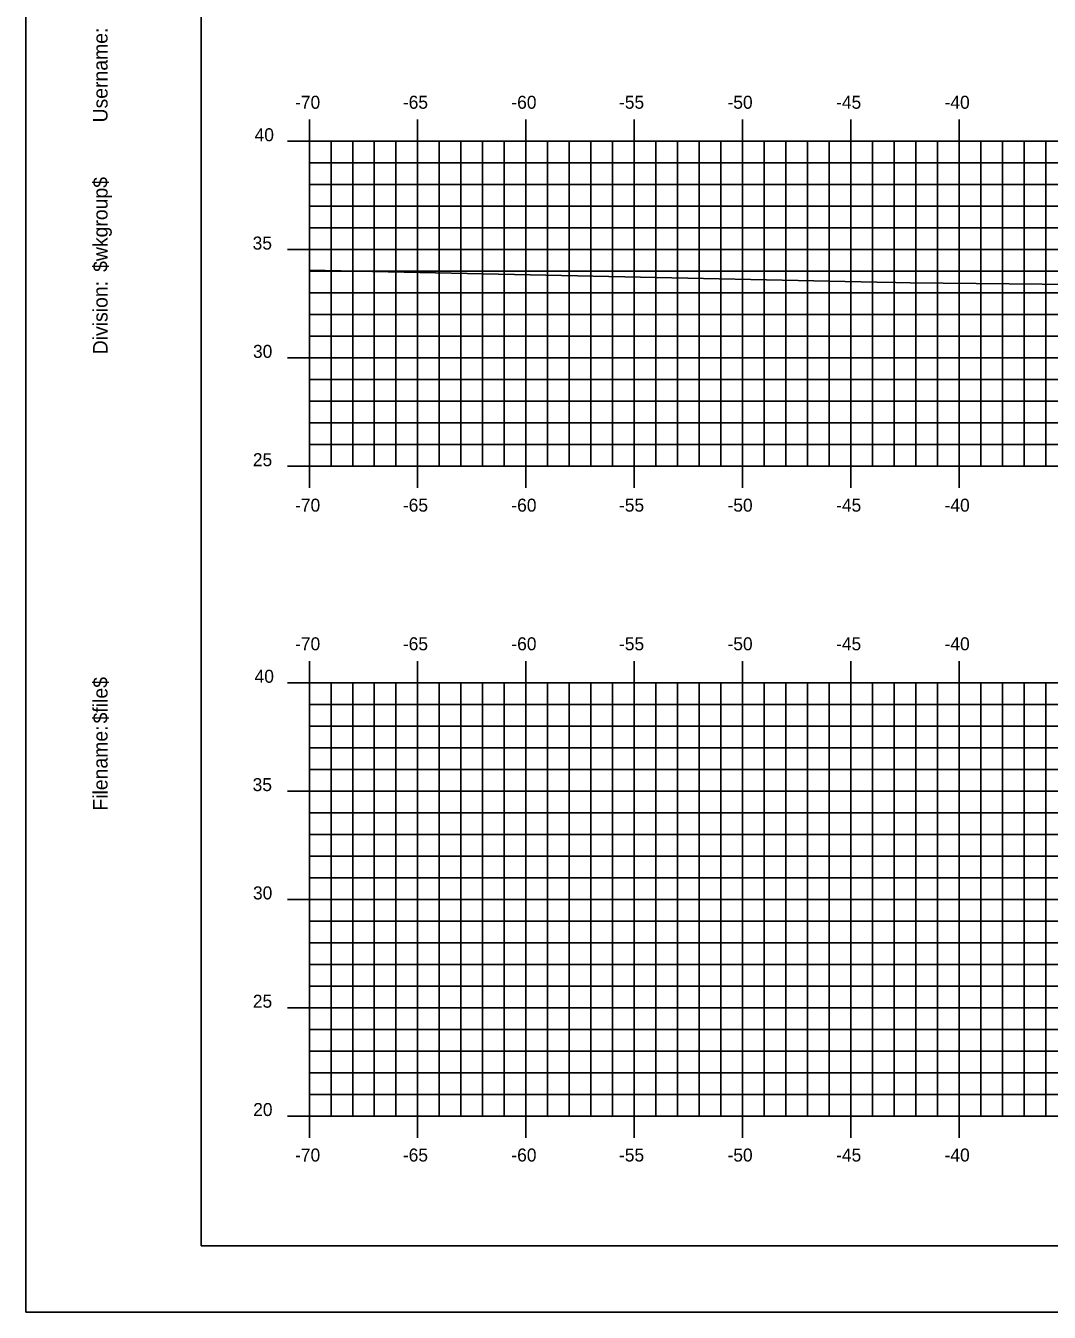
# Model space of a CAD drawing. Extents: x 1024350 to 1024520, y 394697 to 394807.
# Drawn here: x 1024349.9 to 1024397.2, y 394696.5 to 394755.9 of the extents above; entities that cross this region are included whole.
import ezdxf

# ---------------------------------------------------------------- set-up
doc = ezdxf.new("R2010")
doc.units = 0
for name, color, linetype in [('BORDER', 7, 'Continuous'), ('H_V ANNOTATION', 7, 'Continuous'), ('MAJOR', 7, 'Continuous'), ('MINOR', 7, 'Continuous'), ('PLOT BOUNDARY', 7, 'Continuous'), ('S_Roadway_Centerline', 7, 'Continuous')]:
    doc.layers.add(name, color=color, linetype=linetype)

msp = doc.modelspace()

# ---------------------------------------------------------------- linework, layer by layer
at = {"layer": 'BORDER'}
for p, q in [((1024358.002, 394804.607), (1024358.002, 394699.607)), ((1024358.002, 394699.607), (1024518.002, 394699.607))]:
    msp.add_line(p, q, dxfattribs=at)
at = {"layer": 'MAJOR'}
for p, q in [((1024363.002, 394751.609), (1024363.002, 394750.607)), ((1024368.002, 394751.609), (1024368.002, 394750.607)), ((1024373.002, 394751.609), (1024373.002, 394750.607)), ((1024378.002, 394751.609), (1024378.002, 394750.607)), ((1024383.002, 394751.609), (1024383.002, 394750.607)), ((1024388.002, 394751.609), (1024388.002, 394750.607)), ((1024393.002, 394751.609), (1024393.002, 394750.607)), ((1024362, 394750.607), (1024363.002, 394750.607)), ((1024363.002, 394750.607), (1024503.002, 394750.607)), ((1024363.002, 394735.607), (1024363.002, 394750.607)), ((1024368.002, 394735.607), (1024368.002, 394750.607)), ((1024373.002, 394735.607), (1024373.002, 394750.607)), ((1024378.002, 394735.607), (1024378.002, 394750.607)), ((1024383.002, 394735.607), (1024383.002, 394750.607)), ((1024388.002, 394735.607), (1024388.002, 394750.607)), ((1024393.002, 394735.607), (1024393.002, 394750.607)), ((1024362, 394745.607), (1024363.002, 394745.607)), ((1024363.002, 394745.607), (1024503.002, 394745.607)), ((1024362, 394740.607), (1024363.002, 394740.607)), ((1024363.002, 394740.607), (1024503.002, 394740.607)), ((1024362, 394735.607), (1024363.002, 394735.607)), ((1024363.002, 394735.607), (1024503.002, 394735.607)), ((1024363.002, 394734.605), (1024363.002, 394735.607)), ((1024368.002, 394734.605), (1024368.002, 394735.607)), ((1024373.002, 394734.605), (1024373.002, 394735.607)), ((1024378.002, 394734.605), (1024378.002, 394735.607)), ((1024383.002, 394734.605), (1024383.002, 394735.607)), ((1024388.002, 394734.605), (1024388.002, 394735.607)), ((1024393.002, 394734.605), (1024393.002, 394735.607)), ((1024363.002, 394726.609), (1024363.002, 394725.607)), ((1024368.002, 394726.609), (1024368.002, 394725.607)), ((1024373.002, 394726.609), (1024373.002, 394725.607)), ((1024378.002, 394726.609), (1024378.002, 394725.607)), ((1024383.002, 394726.609), (1024383.002, 394725.607)), ((1024388.002, 394726.609), (1024388.002, 394725.607)), ((1024393.002, 394726.609), (1024393.002, 394725.607)), ((1024362, 394725.607), (1024363.002, 394725.607)), ((1024363.002, 394725.607), (1024503.002, 394725.607)), ((1024363.002, 394705.607), (1024363.002, 394725.607)), ((1024368.002, 394705.607), (1024368.002, 394725.607)), ((1024373.002, 394705.607), (1024373.002, 394725.607)), ((1024378.002, 394705.607), (1024378.002, 394725.607)), ((1024383.002, 394705.607), (1024383.002, 394725.607)), ((1024388.002, 394705.607), (1024388.002, 394725.607)), ((1024393.002, 394705.607), (1024393.002, 394725.607)), ((1024362, 394720.607), (1024363.002, 394720.607)), ((1024363.002, 394720.607), (1024503.002, 394720.607)), ((1024362, 394715.607), (1024363.002, 394715.607)), ((1024363.002, 394715.607), (1024503.002, 394715.607)), ((1024362, 394710.607), (1024363.002, 394710.607)), ((1024363.002, 394710.607), (1024503.002, 394710.607)), ((1024362, 394705.607), (1024363.002, 394705.607)), ((1024363.002, 394705.607), (1024503.002, 394705.607)), ((1024363.002, 394704.605), (1024363.002, 394705.607)), ((1024368.002, 394704.605), (1024368.002, 394705.607)), ((1024373.002, 394704.605), (1024373.002, 394705.607)), ((1024378.002, 394704.605), (1024378.002, 394705.607)), ((1024383.002, 394704.605), (1024383.002, 394705.607)), ((1024388.002, 394704.605), (1024388.002, 394705.607)), ((1024393.002, 394704.605), (1024393.002, 394705.607))]:
    msp.add_line(p, q, dxfattribs=at)
at = {"layer": 'MINOR'}
for p, q in [((1024364.002, 394735.607), (1024364.002, 394750.607)), ((1024365.002, 394735.607), (1024365.002, 394750.607)), ((1024366.002, 394735.607), (1024366.002, 394750.607)), ((1024367.002, 394735.607), (1024367.002, 394750.607)), ((1024369.002, 394735.607), (1024369.002, 394750.607)), ((1024370.002, 394735.607), (1024370.002, 394750.607)), ((1024371.002, 394735.607), (1024371.002, 394750.607)), ((1024372.002, 394735.607), (1024372.002, 394750.607)), ((1024374.002, 394735.607), (1024374.002, 394750.607)), ((1024375.002, 394735.607), (1024375.002, 394750.607)), ((1024376.002, 394735.607), (1024376.002, 394750.607)), ((1024377.002, 394735.607), (1024377.002, 394750.607)), ((1024379.002, 394735.607), (1024379.002, 394750.607)), ((1024380.002, 394735.607), (1024380.002, 394750.607)), ((1024381.002, 394735.607), (1024381.002, 394750.607)), ((1024382.002, 394735.607), (1024382.002, 394750.607)), ((1024384.002, 394735.607), (1024384.002, 394750.607)), ((1024385.002, 394735.607), (1024385.002, 394750.607)), ((1024386.002, 394735.607), (1024386.002, 394750.607)), ((1024387.002, 394735.607), (1024387.002, 394750.607)), ((1024389.002, 394735.607), (1024389.002, 394750.607)), ((1024390.002, 394735.607), (1024390.002, 394750.607)), ((1024391.002, 394735.607), (1024391.002, 394750.607)), ((1024392.002, 394735.607), (1024392.002, 394750.607)), ((1024394.002, 394735.607), (1024394.002, 394750.607)), ((1024395.002, 394735.607), (1024395.002, 394750.607)), ((1024396.002, 394735.607), (1024396.002, 394750.607)), ((1024397.002, 394735.607), (1024397.002, 394750.607)), ((1024363.002, 394749.607), (1024503.002, 394749.607)), ((1024363.002, 394749.607), (1024364.004, 394749.607)), ((1024363.002, 394748.607), (1024503.002, 394748.607)), ((1024363.002, 394748.607), (1024364.004, 394748.607)), ((1024363.002, 394747.607), (1024503.002, 394747.607)), ((1024363.002, 394747.607), (1024364.004, 394747.607)), ((1024363.002, 394746.607), (1024503.002, 394746.607)), ((1024363.002, 394746.607), (1024364.004, 394746.607)), ((1024363.002, 394744.607), (1024503.002, 394744.607)), ((1024363.002, 394744.607), (1024364.004, 394744.607)), ((1024363.002, 394743.607), (1024503.002, 394743.607)), ((1024363.002, 394743.607), (1024364.004, 394743.607)), ((1024363.002, 394742.607), (1024503.002, 394742.607)), ((1024363.002, 394742.607), (1024364.004, 394742.607)), ((1024363.002, 394741.607), (1024503.002, 394741.607)), ((1024363.002, 394741.607), (1024364.004, 394741.607)), ((1024363.002, 394739.607), (1024503.002, 394739.607)), ((1024363.002, 394739.607), (1024364.004, 394739.607)), ((1024363.002, 394738.607), (1024503.002, 394738.607)), ((1024363.002, 394738.607), (1024364.004, 394738.607)), ((1024363.002, 394737.607), (1024503.002, 394737.607)), ((1024363.002, 394737.607), (1024364.004, 394737.607)), ((1024363.002, 394736.607), (1024503.002, 394736.607)), ((1024363.002, 394736.607), (1024364.004, 394736.607)), ((1024364.002, 394705.607), (1024364.002, 394725.607)), ((1024365.002, 394705.607), (1024365.002, 394725.607)), ((1024366.002, 394705.607), (1024366.002, 394725.607)), ((1024367.002, 394705.607), (1024367.002, 394725.607)), ((1024369.002, 394705.607), (1024369.002, 394725.607)), ((1024370.002, 394705.607), (1024370.002, 394725.607)), ((1024371.002, 394705.607), (1024371.002, 394725.607)), ((1024372.002, 394705.607), (1024372.002, 394725.607)), ((1024374.002, 394705.607), (1024374.002, 394725.607)), ((1024375.002, 394705.607), (1024375.002, 394725.607)), ((1024376.002, 394705.607), (1024376.002, 394725.607)), ((1024377.002, 394705.607), (1024377.002, 394725.607)), ((1024379.002, 394705.607), (1024379.002, 394725.607)), ((1024380.002, 394705.607), (1024380.002, 394725.607)), ((1024381.002, 394705.607), (1024381.002, 394725.607)), ((1024382.002, 394705.607), (1024382.002, 394725.607)), ((1024384.002, 394705.607), (1024384.002, 394725.607)), ((1024385.002, 394705.607), (1024385.002, 394725.607)), ((1024386.002, 394705.607), (1024386.002, 394725.607)), ((1024387.002, 394705.607), (1024387.002, 394725.607)), ((1024389.002, 394705.607), (1024389.002, 394725.607)), ((1024390.002, 394705.607), (1024390.002, 394725.607)), ((1024391.002, 394705.607), (1024391.002, 394725.607)), ((1024392.002, 394705.607), (1024392.002, 394725.607)), ((1024394.002, 394705.607), (1024394.002, 394725.607)), ((1024395.002, 394705.607), (1024395.002, 394725.607)), ((1024396.002, 394705.607), (1024396.002, 394725.607)), ((1024397.002, 394705.607), (1024397.002, 394725.607)), ((1024363.002, 394724.607), (1024503.002, 394724.607)), ((1024363.002, 394724.607), (1024364.004, 394724.607)), ((1024363.002, 394723.607), (1024503.002, 394723.607)), ((1024363.002, 394723.607), (1024364.004, 394723.607)), ((1024363.002, 394722.607), (1024503.002, 394722.607)), ((1024363.002, 394722.607), (1024364.004, 394722.607)), ((1024363.002, 394721.607), (1024503.002, 394721.607)), ((1024363.002, 394721.607), (1024364.004, 394721.607)), ((1024363.002, 394719.607), (1024503.002, 394719.607)), ((1024363.002, 394719.607), (1024364.004, 394719.607)), ((1024363.002, 394718.607), (1024503.002, 394718.607)), ((1024363.002, 394718.607), (1024364.004, 394718.607)), ((1024363.002, 394717.607), (1024503.002, 394717.607)), ((1024363.002, 394717.607), (1024364.004, 394717.607)), ((1024363.002, 394716.607), (1024503.002, 394716.607)), ((1024363.002, 394716.607), (1024364.004, 394716.607)), ((1024363.002, 394714.607), (1024503.002, 394714.607)), ((1024363.002, 394714.607), (1024364.004, 394714.607)), ((1024363.002, 394713.607), (1024503.002, 394713.607)), ((1024363.002, 394713.607), (1024364.004, 394713.607)), ((1024363.002, 394712.607), (1024503.002, 394712.607)), ((1024363.002, 394712.607), (1024364.004, 394712.607)), ((1024363.002, 394711.607), (1024503.002, 394711.607)), ((1024363.002, 394711.607), (1024364.004, 394711.607)), ((1024363.002, 394709.607), (1024503.002, 394709.607)), ((1024363.002, 394709.607), (1024364.004, 394709.607)), ((1024363.002, 394708.607), (1024503.002, 394708.607)), ((1024363.002, 394708.607), (1024364.004, 394708.607)), ((1024363.002, 394707.607), (1024503.002, 394707.607)), ((1024363.002, 394707.607), (1024364.004, 394707.607)), ((1024363.002, 394706.607), (1024503.002, 394706.607)), ((1024363.002, 394706.607), (1024364.004, 394706.607))]:
    msp.add_line(p, q, dxfattribs=at)
at = {"layer": 'PLOT BOUNDARY'}
msp.add_lwpolyline([(1024349.909, 394696.548), (1024519.909, 394696.548), (1024519.909, 394806.548), (1024349.909, 394806.548)], close=True, dxfattribs=at)
at = {"layer": 'S_Roadway_Centerline'}
msp.add_lwpolyline([(1024363.002, 394744.661), (1024389.193, 394744.097), (1024390.079, 394744.083), (1024390.738, 394744.068), (1024404.458, 394743.926), (1024422.871, 394743.689), (1024423.133, 394743.69), (1024423.252, 394743.69), (1024423.368, 394743.693), (1024423.473, 394743.695), (1024423.535, 394743.696), (1024425.607, 394743.694), (1024452.655, 394743.489), (1024453.91, 394743.47), (1024454.075, 394743.469), (1024454.263, 394743.469), (1024459.693, 394743.513)], dxfattribs=at)

# ---------------------------------------------------------------- texts
at = {"layer": 'BORDER'}
for s, p in [('Username:', (1024353.687, 394751.474)), ('$wkgroup$', (1024353.687, 394744.576)), ('Division:', (1024353.687, 394740.773)), ('$file$', (1024353.687, 394723.732)), ('Filename:', (1024353.687, 394719.705))]:
    msp.add_text(s, height=0.6696, rotation=90, dxfattribs=at).set_placement(p)
at = {"layer": 'H_V ANNOTATION'}
for s, p in [('-70', (1024362.344, 394752.107)), ('-65', (1024367.32, 394752.107)), ('-60', (1024372.328, 394752.107)), ('-55', (1024377.298, 394752.107)), ('-50', (1024382.306, 394752.107)), ('-45', (1024387.32, 394752.107)), ('-40', (1024392.328, 394752.107)), ('40', (1024360.475, 394750.607)), ('35', (1024360.384, 394745.607)), ('30', (1024360.4, 394740.607)), ('25', (1024360.394, 394735.607)), ('-70', (1024362.344, 394733.507)), ('-65', (1024367.32, 394733.507)), ('-60', (1024372.328, 394733.507)), ('-55', (1024377.298, 394733.507)), ('-50', (1024382.306, 394733.507)), ('-45', (1024387.32, 394733.507)), ('-40', (1024392.328, 394733.507)), ('-70', (1024362.344, 394727.107)), ('-65', (1024367.32, 394727.107)), ('-60', (1024372.328, 394727.107)), ('-55', (1024377.298, 394727.107)), ('-50', (1024382.306, 394727.107)), ('-45', (1024387.32, 394727.107)), ('-40', (1024392.328, 394727.107)), ('40', (1024360.475, 394725.607)), ('35', (1024360.384, 394720.607)), ('30', (1024360.4, 394715.607)), ('25', (1024360.394, 394710.607)), ('20', (1024360.41, 394705.607)), ('-70', (1024362.344, 394703.507)), ('-65', (1024367.32, 394703.507)), ('-60', (1024372.328, 394703.507)), ('-55', (1024377.298, 394703.507)), ('-50', (1024382.306, 394703.507)), ('-45', (1024387.32, 394703.507)), ('-40', (1024392.328, 394703.507))]:
    msp.add_text(s, height=0.6, dxfattribs=at).set_placement(p)

doc.saveas('drawing.dxf')
